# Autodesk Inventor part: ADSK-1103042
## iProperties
Shininess: 50.0
Length Units: 11272
Angle Units: 11279
Time Units: 11290
Mass Units: 11286
Length Display Precision: 4
Angle Display Precision: 2
Compacted: True
Created: 2000-11
Part Number: ADSK-1103042
Document SubType Name: Modeling
Description: CONNECTING ROD
Mass: 0.815863 g
Surface Area: 4.69105 cm^2
Volume: 0.301057 cm^3
Density: 2.71 g/cm^3
Material: Aluminum-6061
Density: 0.0
Volumn: 0.0
Area: 0.0
PropertySet Name: Model Information
Control State: 0
Master: False
Checked Out: False
Author: Autodesk, Inc.
